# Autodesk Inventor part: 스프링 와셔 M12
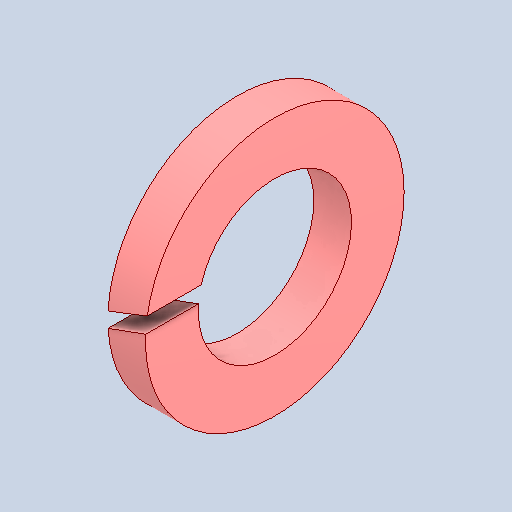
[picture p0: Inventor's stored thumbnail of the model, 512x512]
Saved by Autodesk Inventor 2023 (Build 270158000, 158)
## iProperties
Created: 2025-03
Part Number: 스프링 와셔 M12
Material: 강철, 연강
Description: 스프링 잠금 와셔
Document SubType Name: Modeling
Designer: ADMIN_PC
Density: 7.85 g/cm^3
Appearance: 기본값
Author: jhkim
Sending System: Autodesk Inventor 2025
Preprocessor: ST-DEVELOPER v20
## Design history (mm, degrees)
feature "Solid1"
node "솔리드1"
